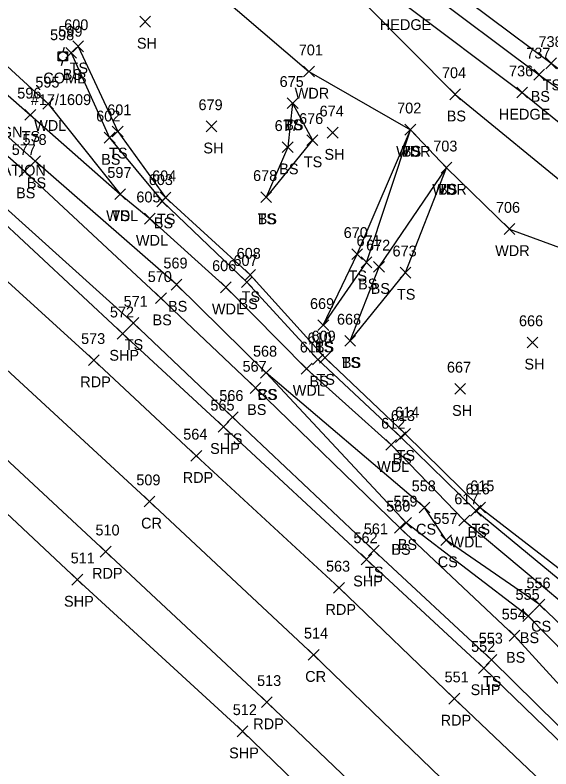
# Model space of a CAD drawing. Extents: x 1611034 to 1613847, y 761049 to 763902.
# Drawn here: x 1611815.8 to 1611914.9, y 763048.6 to 763188 of the extents above; entities that cross this region are included whole.
import ezdxf

# ---------------------------------------------------------------- set-up
doc = ezdxf.new("R2010")
doc.units = 0
for name, color, linetype in [('L_A', 7, 'Continuous'), ('L_I', 7, 'Continuous'), ('L_TIC', 7, 'Continuous'), ('LAHR', 7, 'Continuous'), ('LAWA', 7, 'Continuous'), ('LELB', 7, 'Continuous'), ('P_A', 7, 'Continuous'), ('P_I', 7, 'Continuous'), ('P_TIC', 7, 'Continuous'), ('PET', 7, 'Continuous'), ('PRC', 7, 'Continuous'), ('PSP', 7, 'Continuous'), ('S_A', 7, 'Continuous'), ('S_C', 7, 'Continuous'), ('U_A', 7, 'Continuous'), ('U_C', 7, 'Continuous'), ('U_I', 7, 'Continuous'), ('UP', 7, 'Continuous')]:
    doc.layers.add(name, color=color, linetype=linetype)

msp = doc.modelspace()

# ---------------------------------------------------------------- linework, layer by layer
at = {"layer": 'L_TIC'}
for points in [[(1611838.85, 763185.79), (1611840.85, 763187.79)], [(1611840.85, 763185.79), (1611838.85, 763187.79)], [(1611826.47, 763181.21), (1611828.47, 763183.21)], [(1611828.47, 763181.21), (1611826.47, 763183.21)], [(1611825.18, 763180.01), (1611827.18, 763182.01)], [(1611827.18, 763180.01), (1611825.18, 763182.01)], [(1611913.99, 763178.09), (1611915.99, 763180.09)], [(1611915.99, 763178.09), (1611913.99, 763180.09)], [(1611869.16, 763176.55), (1611871.16, 763178.55)], [(1611871.16, 763176.55), (1611869.16, 763178.55)], [(1611911.74, 763175.97), (1611913.74, 763177.97)], [(1611913.74, 763175.97), (1611911.74, 763177.97)], [(1611896.21, 763172.34), (1611898.21, 763174.34)], [(1611898.21, 763172.34), (1611896.21, 763174.34)], [(1611908.6, 763172.67), (1611910.6, 763174.67)], [(1611910.6, 763172.67), (1611908.6, 763174.67)], [(1611820.91, 763170.59), (1611822.91, 763172.59)], [(1611822.91, 763170.59), (1611820.91, 763172.59)], [(1611866.15, 763170.71), (1611868.15, 763172.71)], [(1611868.15, 763170.71), (1611866.15, 763172.71)], [(1611866.15, 763170.71), (1611868.15, 763172.71)], [(1611868.15, 763170.71), (1611866.15, 763172.71)], [(1611817.61, 763168.56), (1611819.61, 763170.56)], [(1611819.61, 763168.56), (1611817.61, 763170.56)], [(1611833.78, 763165.48), (1611835.78, 763167.48)], [(1611835.78, 763165.48), (1611833.78, 763167.48)], [(1611851.14, 763166.42), (1611853.14, 763168.42)], [(1611853.14, 763166.42), (1611851.14, 763168.42)], [(1611873.55, 763165.25), (1611875.55, 763167.25)], [(1611875.55, 763165.25), (1611873.55, 763167.25)], [(1611887.93, 763165.81), (1611889.93, 763167.81)], [(1611889.93, 763165.81), (1611887.93, 763167.81)], [(1611887.93, 763165.81), (1611889.93, 763167.81)], [(1611889.93, 763165.81), (1611887.93, 763167.81)], [(1611887.93, 763165.81), (1611889.93, 763167.81)], [(1611889.93, 763165.81), (1611887.93, 763167.81)], [(1611832.29, 763164.33), (1611834.29, 763166.33)], [(1611834.29, 763164.33), (1611832.29, 763166.33)], [(1611869.8, 763163.86), (1611871.8, 763165.86)], [(1611871.8, 763163.86), (1611869.8, 763165.86)], [(1611865.23, 763162.56), (1611867.23, 763164.56)], [(1611867.23, 763162.56), (1611865.23, 763164.56)], [(1611818.53, 763159.99), (1611820.53, 763161.99)], [(1611820.53, 763159.99), (1611818.53, 763161.99)], [(1611894.61, 763158.78), (1611896.61, 763160.78)], [(1611896.61, 763158.78), (1611894.61, 763160.78)], [(1611894.61, 763158.78), (1611896.61, 763160.78)], [(1611896.61, 763158.78), (1611894.61, 763160.78)], [(1611894.61, 763158.78), (1611896.61, 763160.78)], [(1611896.61, 763158.78), (1611894.61, 763160.78)], [(1611816.54, 763158.12), (1611818.54, 763160.12)], [(1611818.54, 763158.12), (1611816.54, 763160.12)], [(1611834.23, 763153.9), (1611836.23, 763155.9)], [(1611836.23, 763153.9), (1611834.23, 763155.9)], [(1611834.23, 763153.9), (1611836.23, 763155.9)], [(1611836.23, 763153.9), (1611834.23, 763155.9)], [(1611842.63, 763153.27), (1611844.63, 763155.27)], [(1611844.63, 763153.27), (1611842.63, 763155.27)], [(1611861.24, 763153.32), (1611863.24, 763155.32)], [(1611863.24, 763153.32), (1611861.24, 763155.32)], [(1611861.24, 763153.32), (1611863.24, 763155.32)], [(1611863.24, 763153.32), (1611861.24, 763155.32)], [(1611842.02, 763152.57), (1611844.02, 763154.57)], [(1611844.02, 763152.57), (1611842.02, 763154.57)], [(1611839.73, 763149.36), (1611841.73, 763151.36)], [(1611841.73, 763149.36), (1611839.73, 763151.36)], [(1611906.25, 763147.44), (1611908.25, 763149.44)], [(1611908.25, 763147.44), (1611906.25, 763149.44)], [(1611878.09, 763142.78), (1611880.09, 763144.78)], [(1611880.09, 763142.78), (1611878.09, 763144.78)], [(1611879.81, 763141.27), (1611881.81, 763143.27)], [(1611881.81, 763141.27), (1611879.81, 763143.27)], [(1611882.13, 763140.45), (1611884.13, 763142.45)], [(1611884.13, 763140.45), (1611882.13, 763142.45)], [(1611858.28, 763138.94), (1611860.28, 763140.94)], [(1611860.28, 763138.94), (1611858.28, 763140.94)], [(1611887.04, 763139.37), (1611889.04, 763141.37)], [(1611889.04, 763139.37), (1611887.04, 763141.37)], [(1611857.69, 763137.62), (1611859.69, 763139.62)], [(1611859.69, 763137.62), (1611857.69, 763139.62)], [(1611844.65, 763137.15), (1611846.65, 763139.15)], [(1611846.65, 763137.15), (1611844.65, 763139.15)], [(1611853.8, 763136.66), (1611855.8, 763138.66)], [(1611855.8, 763136.66), (1611853.8, 763138.66)], [(1611841.79, 763134.64), (1611843.79, 763136.64)], [(1611843.79, 763134.64), (1611841.79, 763136.64)], [(1611836.67, 763130.07), (1611838.67, 763132.07)], [(1611838.67, 763130.07), (1611836.67, 763132.07)], [(1611871.82, 763129.65), (1611873.82, 763131.65)], [(1611873.82, 763129.65), (1611871.82, 763131.65)], [(1611871.82, 763129.65), (1611873.82, 763131.65)], [(1611873.82, 763129.65), (1611871.82, 763131.65)], [(1611876.8, 763126.76), (1611878.8, 763128.76)], [(1611878.8, 763126.76), (1611876.8, 763128.76)], [(1611876.8, 763126.76), (1611878.8, 763128.76)], [(1611878.8, 763126.76), (1611876.8, 763128.76)], [(1611910.53, 763126.47), (1611912.53, 763128.47)], [(1611912.53, 763126.47), (1611910.53, 763128.47)], [(1611872.14, 763123.64), (1611874.14, 763125.64)], [(1611874.14, 763123.64), (1611872.14, 763125.64)], [(1611870.83, 763123.3), (1611872.83, 763125.3)], [(1611872.83, 763123.3), (1611870.83, 763125.3)], [(1611861.22, 763120.84), (1611863.22, 763122.84)], [(1611863.22, 763120.84), (1611861.22, 763122.84)], [(1611861.22, 763120.84), (1611863.22, 763122.84)], [(1611863.22, 763120.84), (1611861.22, 763122.84)], [(1611868.74, 763121.61), (1611870.74, 763123.61)], [(1611870.74, 763121.61), (1611868.74, 763123.61)], [(1611859.29, 763118.05), (1611861.29, 763120.05)], [(1611861.29, 763118.05), (1611859.29, 763120.05)], [(1611897.15, 763117.89), (1611899.15, 763119.89)], [(1611899.15, 763117.89), (1611897.15, 763119.89)], [(1611855.04, 763112.65), (1611857.04, 763114.65)], [(1611857.04, 763112.65), (1611855.04, 763114.65)], [(1611886.96, 763109.58), (1611888.96, 763111.58)], [(1611888.96, 763109.58), (1611886.96, 763111.58)], [(1611886.15, 763108.94), (1611888.15, 763110.94)], [(1611888.15, 763108.94), (1611886.15, 763110.94)], [(1611884.36, 763107.52), (1611886.36, 763109.52)], [(1611886.36, 763107.52), (1611884.36, 763109.52)], [(1611890.53, 763095.94), (1611892.53, 763097.94)], [(1611892.53, 763095.94), (1611890.53, 763097.94)], [(1611900.84, 763095.95), (1611902.84, 763097.95)], [(1611902.84, 763095.95), (1611900.84, 763097.95)], [(1611900.05, 763095.37), (1611902.05, 763097.37)], [(1611902.05, 763095.37), (1611900.05, 763097.37)], [(1611887.16, 763093.11), (1611889.16, 763095.11)], [(1611889.16, 763093.11), (1611887.16, 763095.11)], [(1611897.9, 763093.55), (1611899.9, 763095.55)], [(1611899.9, 763093.55), (1611897.9, 763095.55)], [(1611885.96, 763092.2), (1611887.96, 763094.2)], [(1611887.96, 763092.2), (1611885.96, 763094.2)], [(1611894.55, 763089.9), (1611896.55, 763091.9)], [(1611896.55, 763089.9), (1611894.55, 763091.9)], [(1611881.15, 763088), (1611883.15, 763090)], [(1611883.15, 763088), (1611881.15, 763090)], [(1611911.82, 763077.99), (1611913.82, 763079.99)], [(1611913.82, 763077.99), (1611911.82, 763079.99)], [(1611909.74, 763075.87), (1611911.74, 763077.87)], [(1611911.74, 763075.87), (1611909.74, 763077.87)], [(1611907.18, 763072.24), (1611909.18, 763074.24)], [(1611909.18, 763072.24), (1611907.18, 763074.24)], [(1611902.94, 763067.78), (1611904.94, 763069.78)], [(1611904.94, 763067.78), (1611902.94, 763069.78)]]:
    msp.add_lwpolyline(points, dxfattribs=at)
at = {"layer": 'LAHR'}
msp.add_lwpolyline([(1611870.5, 763246), (1611861.19, 763216.3), (1611876.92, 763202.2), (1611887.58, 763190.23), (1611909.6, 763173.67), (1611924.3, 763161.79), (1611933.01, 763152.8), (1611942.84, 763146), (1611944.38, 763148.34), (1611945.72, 763149.4), (1611955.37, 763161.74), (1611966.07, 763176.23)], dxfattribs=at)
at = {"layer": 'LAWA'}
for points in [[(1611802.19, 763242.63), (1611826.4, 763223.06), (1611842.76, 763208.98), (1611848.45, 763196.15), (1611870.16, 763177.55), (1611888.93, 763166.81), (1611895.61, 763159.78), (1611907.25, 763148.44), (1611925.92, 763141.58), (1611941.9, 763130.03), (1611944.3, 763130.53), (1611953.78, 763136.1), (1611962.53, 763149.06), (1611975, 763169.4)], [(1611776.19, 763209.71), (1611798.35, 763193.21), (1611821.91, 763171.59), (1611835.23, 763154.9), (1611840.73, 763150.36), (1611854.8, 763137.66), (1611869.74, 763122.61), (1611885.36, 763108.52), (1611898.9, 763094.55), (1611920.73, 763076.3), (1611936.34, 763060.75), (1611959.95, 763037.9), (1611979.24, 763021.14), (1611992.68, 763010.08), (1612014.52, 762988.49), (1612021.56, 762990.5), (1612027.56, 763011.05)]]:
    msp.add_lwpolyline(points, dxfattribs=at)
at = {"layer": 'LELB'}
for points in [[(1611855.79, 763242.28), (1611845.15, 763223.22), (1611842.76, 763208.98), (1611861.16, 763206.26), (1611872.42, 763198.32), (1611897.21, 763173.34), (1611919.99, 763154.68), (1611938.12, 763138.36), (1611941.9, 763130.03), (1611945.43, 763119.54), (1611962.31, 763107.12), (1611958.31, 763113.02), (1611953.96, 763122.93), (1611951.67, 763129.35), (1611946.1, 763127.17)], [(1611776.19, 763209.71), (1611795.53, 763189.74), (1611818.61, 763169.56), (1611835.23, 763154.9)], [(1611878.59, 763205.7), (1611892.17, 763196.21), (1611914.99, 763179.09), (1611930.29, 763167.67), (1611942.93, 763155.25), (1611945.72, 763149.4)], [(1611878.59, 763205.7), (1611890.96, 763193.26), (1611912.74, 763176.97), (1611927.67, 763166.3), (1611941.9, 763153.84), (1611944.38, 763148.34)], [(1612018.61, 762964.73), (1611994.45, 762990.34), (1611965, 763017.91), (1611936.07, 763051.1), (1611910.74, 763076.87), (1611888.16, 763094.11), (1611862.22, 763121.84), (1611845.65, 763138.15), (1611819.53, 763160.99), (1611794.46, 763183.41), (1611771.91, 763204.52)], [(1612017.14, 762963.27), (1611992.31, 762988.18), (1611962.87, 763016.31), (1611931.63, 763047.56), (1611908.18, 763073.24), (1611886.96, 763093.2), (1611860.29, 763119.05), (1611842.79, 763135.64), (1611817.54, 763159.12), (1611792.58, 763181.1), (1611769.85, 763202.31)], [(1612014.39, 762960.1), (1611988.81, 762984.91), (1611960.67, 763014.03), (1611928.51, 763044.56), (1611903.94, 763068.78), (1611882.15, 763089), (1611856.04, 763113.65), (1611837.67, 763131.07), (1611812.66, 763153.54), (1611788.39, 763176.44), (1611765.16, 763197.77)], [(1611827.47, 763182.21), (1611834.78, 763166.48), (1611843.63, 763154.27), (1611859.28, 763139.94), (1611873.14, 763124.64), (1611887.96, 763110.58), (1611901.84, 763096.95), (1611924.35, 763079.56), (1611938.78, 763063.64), (1611947.53, 763063.29), (1611949.88, 763063.93)], [(1611826.18, 763181.01), (1611833.29, 763165.33), (1611843.02, 763153.57), (1611858.69, 763138.62), (1611871.83, 763124.3), (1611887.15, 763109.94), (1611901.05, 763096.37), (1611922.98, 763078.25), (1611938.18, 763062.8), (1611947.71, 763061.88), (1611949.88, 763063.93)], [(1611867.15, 763171.71), (1611870.8, 763164.86), (1611862.24, 763154.32)], [(1611867.15, 763171.71), (1611866.23, 763163.56), (1611862.24, 763154.32)], [(1611872.82, 763130.65), (1611879.09, 763143.78), (1611888.93, 763166.81)], [(1611872.82, 763130.65), (1611880.81, 763142.27), (1611888.93, 763166.81)], [(1611877.8, 763127.76), (1611888.04, 763140.37), (1611895.61, 763159.78)], [(1611877.8, 763127.76), (1611883.13, 763141.45), (1611895.61, 763159.78)], [(1611994.45, 762990.34), (1611968.15, 763021.56), (1611939.94, 763053.04), (1611912.82, 763078.99), (1611895.55, 763090.9), (1611891.53, 763096.94), (1611862.22, 763121.84)]]:
    msp.add_lwpolyline(points, dxfattribs=at)
at = {"layer": 'P_TIC'}
for points in [[(1611834.7, 763128.09), (1611836.7, 763130.09)], [(1611836.7, 763128.09), (1611834.7, 763130.09)], [(1611829.38, 763123.18), (1611831.38, 763125.18)], [(1611831.38, 763123.18), (1611829.38, 763125.18)], [(1611853.34, 763110.86), (1611855.34, 763112.86)], [(1611855.34, 763110.86), (1611853.34, 763112.86)], [(1611848.32, 763105.5), (1611850.32, 763107.5)], [(1611850.32, 763105.5), (1611848.32, 763107.5)], [(1611839.68, 763097.05), (1611841.68, 763099.05)], [(1611841.68, 763097.05), (1611839.68, 763099.05)], [(1611831.55, 763087.78), (1611833.55, 763089.78)], [(1611833.55, 763087.78), (1611831.55, 763089.78)], [(1611879.81, 763086.35), (1611881.81, 763088.35)], [(1611881.81, 763086.35), (1611879.81, 763088.35)], [(1611826.31, 763082.61), (1611828.31, 763084.61)], [(1611828.31, 763082.61), (1611826.31, 763084.61)], [(1611874.73, 763081.09), (1611876.73, 763083.09)], [(1611876.73, 763081.09), (1611874.73, 763083.09)], [(1611870.03, 763068.71), (1611872.03, 763070.71)], [(1611872.03, 763068.71), (1611870.03, 763070.71)], [(1611901.53, 763066.25), (1611903.53, 763068.25)], [(1611903.53, 763066.25), (1611901.53, 763068.25)], [(1611861.37, 763059.94), (1611863.37, 763061.94)], [(1611863.37, 763059.94), (1611861.37, 763061.94)], [(1611896.05, 763060.61), (1611898.05, 763062.61)], [(1611898.05, 763060.61), (1611896.05, 763062.61)], [(1611856.87, 763054.56), (1611858.87, 763056.56)], [(1611858.87, 763054.56), (1611856.87, 763056.56)]]:
    msp.add_lwpolyline(points, dxfattribs=at)
at = {"layer": 'PET'}
for points in [[(1612007.41, 762953.69), (1611981.88, 762978.72), (1611953.4, 763007), (1611921.8, 763038.1), (1611897.05, 763061.61), (1611875.73, 763082.09), (1611849.32, 763106.5), (1611830.38, 763124.18), (1611806.13, 763146.18), (1611781.49, 763169.41), (1611758.07, 763190.79)], [(1611742.95, 763171.95), (1611773.98, 763143.16), (1611800.57, 763118.45), (1611832.55, 763088.78), (1611862.37, 763060.94), (1611895.49, 763029.35), (1611927.37, 762998.83), (1611963.34, 762963.21), (1611989.07, 762936.88)]]:
    msp.add_lwpolyline(points, dxfattribs=at)
at = {"layer": 'PRC'}
msp.add_lwpolyline([(1611750.53, 763181.03), (1611781.55, 763152.75), (1611808.47, 763127.7), (1611840.68, 763098.05), (1611871.03, 763069.71), (1611903.68, 763038.16), (1611935.64, 763007.53), (1611970.73, 762973.2), (1611998.37, 762945.17)], dxfattribs=at)
at = {"layer": 'PSP'}
for points in [[(1612013.06, 762958.69), (1611987.98, 762983.85), (1611959.05, 763012.61), (1611927.06, 763043.5), (1611902.53, 763067.25), (1611880.81, 763087.35), (1611854.34, 763111.86), (1611835.7, 763129.09), (1611811.01, 763152.07), (1611786.17, 763174.66), (1611763.42, 763195.74)], [(1611737.63, 763166.68), (1611769.14, 763137.5), (1611795.96, 763113), (1611827.31, 763083.61), (1611857.87, 763055.56), (1611890.74, 763023.79), (1611921.91, 762994.17), (1611958.53, 762957.84), (1611984.49, 762931.79)]]:
    msp.add_lwpolyline(points, dxfattribs=at)
at = {"layer": 'UP'}
for p, q in [((1611823.8, 763179.53), (1611823.8, 763181.2)), ((1611823.8, 763181.2), (1611825.47, 763181.2)), ((1611824.89, 763182.03), (1611824.64, 763181.2)), ((1611825.47, 763181.2), (1611825.47, 763179.53)), ((1611824.64, 763180.36), (1611824.64, 763180.36)), ((1611825.47, 763179.53), (1611823.8, 763179.53)), ((1611824.39, 763178.7), (1611824.64, 763179.53))]:
    msp.add_line(p, q, dxfattribs=at)
msp.add_circle((1611824.64, 763180.36), 0.833, dxfattribs=at)

# ---------------------------------------------------------------- texts
at = {"layer": 'L_A'}
for s, p in [('HEDGE', (1611883.28, 763185.23)), ('SH', (1611838.34, 763181.79)), ('TS', (1611825.88, 763177.21)), ('BS', (1611824.62, 763176.01)), ('TS', (1611913.4, 763174.09)), ('WDR', (1611867.52, 763172.55)), ('BS', (1611911.18, 763171.97)), ('BS', (1611895.65, 763168.34)), ('HEDGE', (1611905.3, 763168.67)), ('TS', (1611865.56, 763166.71)), ('BS', (1611865.59, 763166.71)), ('WDL', (1611819.33, 763166.59)), ('TS', (1611817.02, 763164.56)), ('SH', (1611850.63, 763162.42)), ('TS', (1611833.19, 763161.48)), ('SH', (1611873.03, 763161.25)), ('WDR', (1611886.29, 763161.81)), ('TS', (1611887.34, 763161.81)), ('BS', (1611887.37, 763161.81)), ('BS', (1611831.73, 763160.33)), ('TS', (1611869.21, 763159.86)), ('BS', (1611864.67, 763158.56)), ('BS', (1611817.98, 763155.99)), ('BS', (1611815.98, 763154.12)), ('WDR', (1611892.97, 763154.78)), ('TS', (1611894.01, 763154.78)), ('BS', (1611894.05, 763154.78)), ('WDL', (1611832.65, 763149.9)), ('TS', (1611833.64, 763149.9)), ('BS', (1611841.46, 763148.57)), ('TS', (1611842.04, 763149.27)), ('TS', (1611860.65, 763149.32)), ('BS', (1611860.68, 763149.32)), ('WDL', (1611838.15, 763145.36)), ('WDR', (1611904.61, 763143.44)), ('TS', (1611877.49, 763138.78)), ('BS', (1611879.25, 763137.27)), ('BS', (1611881.58, 763136.45)), ('TS', (1611857.69, 763134.94)), ('TS', (1611886.44, 763135.37)), ('BS', (1611844.09, 763133.15)), ('BS', (1611857.13, 763133.62)), ('WDL', (1611852.21, 763132.66)), ('BS', (1611841.23, 763130.64)), ('TS', (1611836.08, 763126.07)), ('TS', (1611871.23, 763125.65)), ('BS', (1611871.26, 763125.65)), ('TS', (1611876.21, 763122.76)), ('BS', (1611876.25, 763122.76)), ('SH', (1611910.02, 763122.47)), ('BS', (1611870.27, 763119.3)), ('TS', (1611871.55, 763119.64)), ('CS', (1611860.66, 763116.84)), ('BS', (1611860.66, 763116.84)), ('WDL', (1611867.16, 763117.61)), ('BS', (1611858.73, 763114.05)), ('SH', (1611896.64, 763113.89)), ('TS', (1611854.45, 763108.65)), ('TS', (1611886.37, 763105.58)), ('BS', (1611885.6, 763104.94)), ('WDL', (1611882.78, 763103.52)), ('CS', (1611889.97, 763091.94)), ('BS', (1611899.49, 763091.37)), ('TS', (1611900.25, 763091.95)), ('BS', (1611886.6, 763089.11)), ('WDL', (1611896.32, 763089.55)), ('BS', (1611885.4, 763088.2)), ('CS', (1611893.99, 763085.9)), ('TS', (1611880.56, 763084)), ('CS', (1611911.26, 763073.99)), ('BS', (1611909.18, 763071.87)), ('BS', (1611906.62, 763068.24)), ('TS', (1611902.34, 763063.78))]:
    msp.add_text(s, height=2, dxfattribs=at).set_placement(p)
at = {"layer": 'L_I'}
for s, p in [('600', (1611824.89, 763185.21)), ('599', (1611823.81, 763184.01)), ('738', (1611912.63, 763182.09)), ('701', (1611868.28, 763180.55)), ('737', (1611910.37, 763179.97)), ('704', (1611894.77, 763176.34)), ('736', (1611907.18, 763176.67)), ('595', (1611819.55, 763174.59)), ('675', (1611864.74, 763174.71)), ('675', (1611864.74, 763174.71)), ('596', (1611816.2, 763172.56)), ('601', (1611832.85, 763169.48)), ('679', (1611849.73, 763170.42)), ('702', (1611886.48, 763169.81)), ('702', (1611886.48, 763169.81)), ('702', (1611886.48, 763169.81)), ('602', (1611830.8, 763168.33)), ('674', (1611872.14, 763169.25)), ('676', (1611868.34, 763167.86)), ('677', (1611863.82, 763166.56)), ('578', (1611817.17, 763163.99)), ('703', (1611893.16, 763162.78)), ('703', (1611893.16, 763162.78)), ('703', (1611893.16, 763162.78)), ('577', (1611815.18, 763162.12)), ('597', (1611832.87, 763157.9)), ('597', (1611832.87, 763157.9)), ('604', (1611841.15, 763157.27)), ('678', (1611859.83, 763157.32)), ('678', (1611859.83, 763157.32)), ('603', (1611840.53, 763156.57)), ('605', (1611838.24, 763153.36)), ('706', (1611904.75, 763151.44)), ('670', (1611876.59, 763146.78)), ('671', (1611878.97, 763145.27)), ('672', (1611880.73, 763144.45)), ('608', (1611856.79, 763142.94)), ('673', (1611885.63, 763143.37)), ('607', (1611856.2, 763141.62)), ('569', (1611843.24, 763141.15)), ('606', (1611852.25, 763140.66)), ('570', (1611840.34, 763138.64)), ('571', (1611835.88, 763134.07)), ('669', (1611870.36, 763133.65)), ('669', (1611870.36, 763133.65)), ('668', (1611875.35, 763130.76)), ('668', (1611875.35, 763130.76)), ('666', (1611909.02, 763130.47)), ('609', (1611870.64, 763127.64)), ('610', (1611869.9, 763127.3)), ('568', (1611859.81, 763124.84)), ('568', (1611859.81, 763124.84)), ('611', (1611868.47, 763125.61)), ('567', (1611857.88, 763122.05)), ('667', (1611895.69, 763121.89)), ('566', (1611853.58, 763116.65)), ('613', (1611885.31, 763112.94)), ('614', (1611886.11, 763113.58)), ('612', (1611883.52, 763111.52)), ('558', (1611889.17, 763099.94)), ('615', (1611900, 763099.95)), ('616', (1611899.15, 763099.37)), ('559', (1611885.79, 763097.11)), ('617', (1611897.06, 763097.55)), ('560', (1611884.46, 763096.2)), ('557', (1611893.19, 763093.9)), ('561', (1611880.31, 763092)), ('556', (1611910.4, 763081.99)), ('555', (1611908.38, 763079.87)), ('554', (1611905.82, 763076.24)), ('553', (1611901.57, 763071.78))]:
    msp.add_text(s, height=2, dxfattribs=at).set_placement(p)
at = {"layer": 'P_A'}
for s, p in [('SHP', (1611833.24, 763124.09)), ('RDP', (1611827.86, 763119.18)), ('SHP', (1611851.88, 763106.86)), ('RDP', (1611846.81, 763101.5)), ('CR', (1611839.11, 763093.05)), ('RDP', (1611830.04, 763083.78)), ('SHP', (1611878.35, 763082.35)), ('SHP', (1611824.85, 763078.61)), ('RDP', (1611873.22, 763077.09)), ('CR', (1611869.47, 763064.71)), ('SHP', (1611900.07, 763062.25)), ('RDP', (1611894.53, 763056.61)), ('RDP', (1611859.86, 763055.94)), ('SHP', (1611855.4, 763050.56))]:
    msp.add_text(s, height=2, dxfattribs=at).set_placement(p)
at = {"layer": 'P_I'}
for s, p in [('572', (1611833.34, 763132.09)), ('573', (1611828.01, 763127.18)), ('565', (1611851.93, 763114.86)), ('564', (1611846.91, 763109.5)), ('509', (1611838.23, 763101.05)), ('510', (1611830.67, 763091.78)), ('562', (1611878.4, 763090.35)), ('511', (1611826.08, 763086.61)), ('563', (1611873.32, 763085.09)), ('514', (1611869.24, 763072.71)), ('552', (1611900.17, 763070.25)), ('513', (1611860.57, 763063.94)), ('551', (1611895.25, 763064.61)), ('512', (1611856.07, 763058.56))]:
    msp.add_text(s, height=2, dxfattribs=at).set_placement(p)
at = {"layer": 'S_A'}
msp.add_text('SIGN', height=2, dxfattribs=at).set_placement((1611810.64, 763165.38))
at = {"layer": 'S_C'}
msp.add_text('INFORMATION', height=2, dxfattribs=at).set_placement((1611802.77, 763158.31))
at = {"layer": 'U_A'}
msp.add_text('COMB', height=2, dxfattribs=at).set_placement((1611821.02, 763175.36))
at = {"layer": 'U_C'}
msp.add_text('#17/1609', height=2, dxfattribs=at).set_placement((1611818.71, 763171.36))
at = {"layer": 'U_I'}
msp.add_text('598', height=2, dxfattribs=at).set_placement((1611822.27, 763183.36))

doc.saveas('drawing.dxf')
